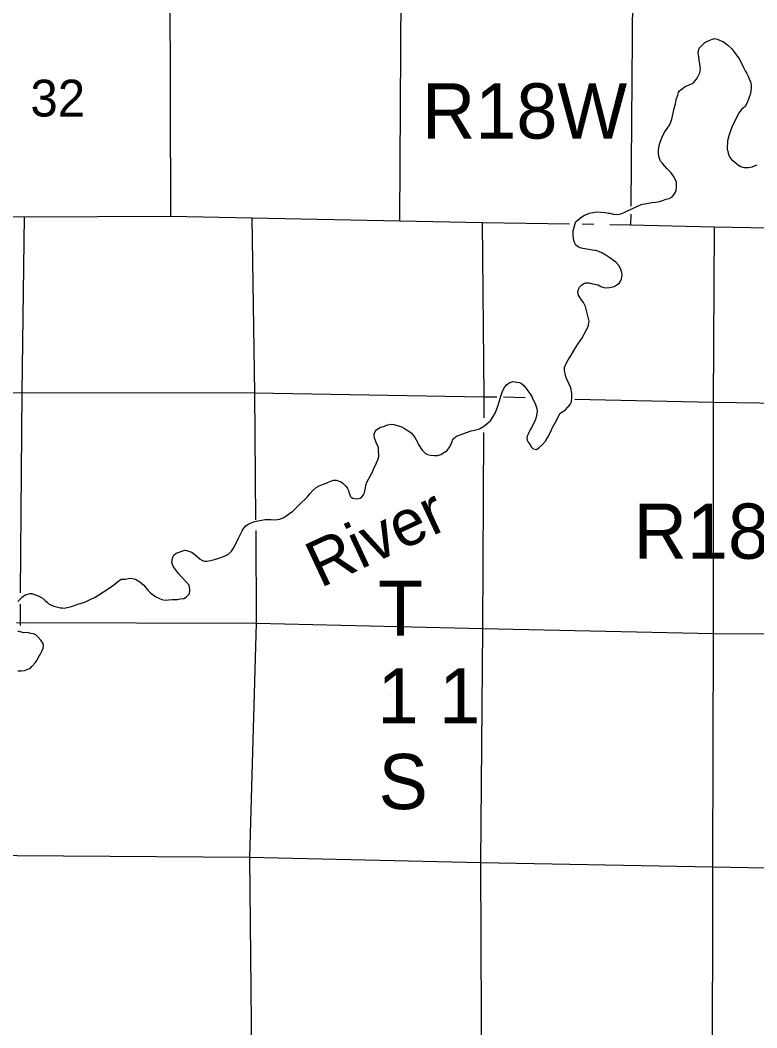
# Model space of a CAD drawing. Extents: x 369523 to 838377, y 495025 to 936819.
# Drawn here: x 613164 to 630067, y 646707 to 669834 of the extents above; entities that cross this region are included whole.
import ezdxf

# ---------------------------------------------------------------- set-up
doc = ezdxf.new("R2010")
doc.units = 0
for name, color, linetype in [('21', 7, 'Continuous'), ('Level 10', 7, 'Continuous'), ('Level 15', 7, 'Continuous'), ('Level 22', 7, 'Continuous'), ('Level 6', 7, 'Continuous')]:
    doc.layers.add(name, color=color, linetype=linetype)

msp = doc.modelspace()

# ---------------------------------------------------------------- linework, layer by layer
at = {"layer": '21'}
msp.add_line((621695, 654327), (621695, 654327), dxfattribs=at)
at = {"layer": 'Level 15'}
for points in [[(605886, 665418), (607991, 665418), (611148, 665368), (613262, 665320), (616612, 665336), (618481, 665296), (621877, 665231), (623770, 665192), (625765, 665158)], [(626061, 665160), (626325, 665151)], [(626693, 665141), (627168, 665140), (629092, 665093), (632435, 665026), (634448, 665035), (636918, 665073)]]:
    msp.add_lwpolyline(points, dxfattribs=at)
at = {"layer": 'Level 22'}
for points in [[(616654, 686505), (616700, 681163), (616598, 675885), (616601, 670709), (616612, 665336)], [(621877, 665231), (621904, 670478), (621874, 675814), (621911, 681087), (621962, 686355)], [(627265, 686234), (627212, 680945), (627217, 675651), (627216, 670404), (627179, 665566)], [(613171, 656688), (613207, 661290), (613262, 665320)], [(618481, 665296), (618538, 661278), (618566, 658369)], [(623812, 660705), (623809, 661193), (623770, 665192)], [(627175, 665382), (627168, 665140)], [(629092, 665093), (629069, 661056), (629065, 655755), (629049, 650405), (629042, 645132), (629075, 639773)], [(602718, 661287), (607982, 661235), (613207, 661290), (618538, 661278), (623799, 661189), (624103, 661186)], [(624755, 661168), (624257, 661183)], [(640672, 661007), (639673, 661005), (634435, 660986), (629069, 661056), (625892, 661130)], [(623804, 639853), (623760, 645102), (623738, 650500), (623784, 655875), (623805, 660371)], [(618570, 658123), (618578, 655993), (618427, 650623), (618478, 645324), (618463, 640081)], [(613172, 655944), (613175, 656434)], [(613081, 656010), (618578, 655993), (623784, 655875), (629065, 655755), (634462, 655732), (639666, 655759), (643998, 655781)], [(607915, 650684), (613094, 650662), (618427, 650623), (623738, 650500), (629049, 650405), (634411, 650303), (639697, 650207)]]:
    msp.add_lwpolyline(points, dxfattribs=at)
at = {"layer": 'Level 6'}
for points in [[(627810, 666861), (627828, 666961), (627851, 667037), (627884, 667136), (627952, 667261), (628010, 667348), (628065, 667427), (628090, 667478), (628119, 667562), (628172, 667807), (628198, 667912), (628219, 668004), (628251, 668115), (628272, 668177), (628294, 668210), (628424, 668314), (628603, 668388), (628685, 668480), (628710, 668530), (628761, 668629), (628776, 668719), (628762, 668835), (628745, 668915), (628734, 669001), (628721, 669071), (628730, 669137), (628755, 669200), (628796, 669248), (628847, 669293), (628873, 669318), (628988, 669373), (629028, 669388), (629099, 669411), (629159, 669400), (629304, 669336), (629395, 669265), (629492, 669175), (629563, 669084), (629616, 669010), (629663, 668953), (629694, 668885), (629741, 668802), (629763, 668750), (629803, 668673), (629837, 668607), (629868, 668552), (629893, 668488), (629922, 668418), (629937, 668350), (629938, 668284), (629931, 668214), (629924, 668150), (629887, 668043), (629843, 667933), (629802, 667854), (629759, 667819), (629719, 667781), (629660, 667716), (629590, 667584), (629497, 667377), (629428, 667181), (629394, 667063), (629387, 666882), (629410, 666781), (629443, 666701), (629484, 666640), (629555, 666583), (629615, 666527), (629694, 666475), (629776, 666456), (629876, 666451), (629960, 666467), (630013, 666491), (630073, 666514)], [(627810, 666861), (627828, 666961), (627851, 667037), (627884, 667136), (627952, 667261), (628010, 667348), (628065, 667427), (628090, 667478), (628119, 667562), (628172, 667807), (628198, 667912), (628219, 668004), (628251, 668115), (628272, 668177), (628294, 668210), (628424, 668314), (628603, 668388), (628685, 668480), (628710, 668530), (628761, 668629), (628776, 668719), (628762, 668835), (628745, 668915), (628734, 669001), (628721, 669071), (628730, 669137), (628755, 669200), (628796, 669248), (628847, 669293), (628873, 669318), (628988, 669373), (629028, 669388), (629099, 669411), (629159, 669400), (629304, 669336), (629395, 669265), (629492, 669175), (629563, 669084), (629616, 669010), (629663, 668953), (629694, 668885), (629741, 668802), (629763, 668750), (629803, 668673), (629837, 668607), (629868, 668552), (629893, 668488), (629922, 668418), (629937, 668350), (629938, 668284), (629931, 668214), (629924, 668150), (629887, 668043), (629843, 667933), (629802, 667854), (629759, 667819), (629719, 667781), (629660, 667716), (629590, 667584), (629497, 667377), (629428, 667181), (629394, 667063), (629387, 666882), (629410, 666781), (629443, 666701), (629484, 666640), (629555, 666583), (629615, 666527), (629694, 666475), (629776, 666456), (629876, 666451), (629960, 666467), (630013, 666491), (630073, 666514)], [(626109, 662626), (626194, 662801), (626222, 662928), (626136, 663261), (626088, 663354), (626040, 663420), (626011, 663459), (625988, 663499), (625970, 663537), (625957, 663599), (625984, 663679), (626001, 663708), (626033, 663744), (626049, 663756), (626092, 663785), (626124, 663799), (626142, 663802), (626174, 663802), (626222, 663803), (626300, 663782), (626424, 663756), (626491, 663719), (626553, 663702), (626603, 663693), (626683, 663696), (626770, 663713), (626808, 663728), (626853, 663762), (626885, 663783), (626913, 663805), (626932, 663832), (626961, 663894), (626974, 663980), (626967, 664044), (626946, 664112), (626905, 664194), (626830, 664281), (626691, 664379), (626600, 664443), (626524, 664484), (626443, 664523), (626371, 664546), (626287, 664557), (626163, 664575), (626075, 664594), (626015, 664611), (625968, 664634), (625916, 664673), (625889, 664713), (625868, 664777), (625851, 664895), (625853, 664999), (625901, 665164), (625924, 665218), (625958, 665247), (626021, 665294), (626054, 665320), (626112, 665355), (626173, 665378), (626223, 665405), (626342, 665429), (626410, 665434), (626488, 665431), (626590, 665416), (626654, 665407), (626698, 665402), (626770, 665385), (626840, 665376), (626910, 665383), (626970, 665400), (627039, 665429), (627081, 665448), (627412, 665605), (627450, 665612), (627544, 665623), (627655, 665649), (627739, 665654), (627793, 665663), (627831, 665669), (627900, 665693), (627988, 665722), (628053, 665741), (628125, 665778), (628164, 665825), (628199, 665883), (628216, 665930), (628227, 665984), (628227, 666046), (628222, 666106), (628207, 666156), (628152, 666257), (628091, 666338), (628054, 666376), (628001, 666431), (627949, 666490), (627898, 666558), (627884, 666569), (627857, 666597), (627826, 666679), (627809, 666758), (627810, 666861)], [(626109, 662626), (626194, 662801), (626222, 662928), (626136, 663261), (626088, 663354), (626040, 663420), (626011, 663459), (625988, 663499), (625970, 663537), (625957, 663599), (625984, 663679), (626001, 663708), (626033, 663744), (626049, 663756), (626092, 663785), (626124, 663799), (626142, 663802), (626174, 663802), (626222, 663803), (626300, 663782), (626424, 663756), (626491, 663719), (626553, 663702), (626603, 663693), (626683, 663696), (626770, 663713), (626808, 663728), (626853, 663762), (626885, 663783), (626913, 663805), (626932, 663832), (626961, 663894), (626974, 663980), (626967, 664044), (626946, 664112), (626905, 664194), (626830, 664281), (626691, 664379), (626600, 664443), (626524, 664484), (626443, 664523), (626371, 664546), (626287, 664557), (626163, 664575), (626075, 664594), (626015, 664611), (625968, 664634), (625916, 664673), (625889, 664713), (625868, 664777), (625851, 664895), (625853, 664999), (625901, 665164), (625924, 665218), (625958, 665247), (626021, 665294), (626054, 665320), (626112, 665355), (626173, 665378), (626223, 665405), (626342, 665429), (626410, 665434), (626488, 665431), (626590, 665416), (626654, 665407), (626698, 665402), (626770, 665385), (626840, 665376), (626910, 665383), (626970, 665400), (627039, 665429), (627081, 665448), (627412, 665605), (627450, 665612), (627544, 665623), (627655, 665649), (627739, 665654), (627793, 665663), (627831, 665669), (627900, 665693), (627988, 665722), (628053, 665741), (628125, 665778), (628164, 665825), (628199, 665883), (628216, 665930), (628227, 665984), (628227, 666046), (628222, 666106), (628207, 666156), (628152, 666257), (628091, 666338), (628054, 666376), (628001, 666431), (627949, 666490), (627898, 666558), (627884, 666569), (627857, 666597), (627826, 666679), (627809, 666758), (627810, 666861)], [(622332, 660048), (622356, 660012), (622389, 659966), (622425, 659925), (622468, 659892), (622514, 659866), (622582, 659847), (622670, 659843), (622740, 659846), (622817, 659863), (622901, 659922), (622964, 659961), (623017, 660032), (623044, 660085), (623077, 660163), (623088, 660195), (623114, 660232), (623135, 660256), (623177, 660289), (623407, 660374), (623515, 660406), (623598, 660425), (623702, 660455), (623795, 660512), (623882, 660574), (623953, 660641), (624017, 660734), (624070, 660833), (624123, 660978), (624164, 661101), (624196, 661205), (624217, 661272), (624250, 661348), (624287, 661415), (624324, 661461), (624350, 661484), (624374, 661504), (624399, 661515), (624431, 661529), (624465, 661538), (624525, 661535), (624563, 661527), (624621, 661518), (624667, 661493), (624730, 661440), (624793, 661356), (624862, 661267), (624911, 661184), (624926, 661138), (624979, 661035), (625004, 660965), (625023, 660911), (625026, 660865), (625022, 660809), (625004, 660725), (624979, 660644), (624954, 660592), (624917, 660521), (624891, 660473), (624866, 660430), (624837, 660368), (624819, 660336), (624794, 660285), (624791, 660231), (624796, 660191), (624820, 660147), (624867, 660090), (624900, 660036), (624930, 660003), (624946, 659995), (625008, 659982), (625075, 660023), (625148, 660092), (625221, 660175), (625272, 660262), (625324, 660363), (625390, 660498), (625450, 660611), (625491, 660694), (625546, 660807), (625674, 660893), (625784, 661015), (625811, 661077), (625826, 661182), (625820, 661276), (625797, 661396), (625760, 661477), (625710, 661591), (625687, 661646), (625675, 661688), (625666, 661726), (625655, 661786), (625655, 661830), (625656, 661864), (625689, 661951), (625742, 662036), (625798, 662133), (625882, 662272), (625962, 662399), (626048, 662525), (626109, 662626)], [(622332, 660048), (622356, 660012), (622389, 659966), (622425, 659925), (622468, 659892), (622514, 659866), (622582, 659847), (622670, 659843), (622740, 659846), (622817, 659863), (622901, 659922), (622964, 659961), (623017, 660032), (623044, 660085), (623077, 660163), (623088, 660195), (623114, 660232), (623135, 660256), (623177, 660289), (623407, 660374), (623515, 660406), (623598, 660425), (623702, 660455), (623795, 660512), (623882, 660574), (623953, 660641), (624017, 660734), (624070, 660833), (624123, 660978), (624164, 661101), (624196, 661205), (624217, 661272), (624250, 661348), (624287, 661415), (624324, 661461), (624350, 661484), (624374, 661504), (624399, 661515), (624431, 661529), (624465, 661538), (624525, 661535), (624563, 661527), (624621, 661518), (624667, 661493), (624730, 661440), (624793, 661356), (624862, 661267), (624911, 661184), (624926, 661138), (624979, 661035), (625004, 660965), (625023, 660911), (625026, 660865), (625022, 660809), (625004, 660725), (624979, 660644), (624954, 660592), (624917, 660521), (624891, 660473), (624866, 660430), (624837, 660368), (624819, 660336), (624794, 660285), (624791, 660231), (624796, 660191), (624820, 660147), (624867, 660090), (624900, 660036), (624930, 660003), (624946, 659995), (625008, 659982), (625075, 660023), (625148, 660092), (625221, 660175), (625272, 660262), (625324, 660363), (625390, 660498), (625450, 660611), (625491, 660694), (625546, 660807), (625674, 660893), (625784, 661015), (625811, 661077), (625826, 661182), (625820, 661276), (625797, 661396), (625760, 661477), (625710, 661591), (625687, 661646), (625675, 661688), (625666, 661726), (625655, 661786), (625655, 661830), (625656, 661864), (625689, 661951), (625742, 662036), (625798, 662133), (625882, 662272), (625962, 662399), (626048, 662525), (626109, 662626)], [(617349, 657431), (617395, 657420), (617447, 657421), (617529, 657436), (617626, 657458), (617700, 657481), (617789, 657512), (617885, 657550), (617944, 657579), (618011, 657644), (618058, 657717), (618110, 657813), (618172, 657945), (618209, 658023), (618256, 658112), (618297, 658177), (618342, 658227), (618396, 658264), (618447, 658293), (618521, 658320), (618618, 658346), (618708, 658359), (618781, 658372), (618847, 658375), (618921, 658370), (618993, 658365), (619065, 658372), (619121, 658381), (619214, 658423), (619418, 658564), (619548, 658694), (619626, 658769), (619693, 658833), (619748, 658887), (619821, 658967), (619878, 659036), (619959, 659105), (620026, 659146), (620098, 659175), (620169, 659202), (620217, 659223), (620292, 659256), (620350, 659273), (620414, 659276), (620532, 659236), (620569, 659206), (620605, 659169), (620635, 659141), (620670, 659098), (620686, 659070), (620695, 659038), (620703, 659000), (620726, 658940), (620734, 658916), (620745, 658902), (620761, 658885), (620797, 658867), (620839, 658852), (620889, 658847), (620933, 658853), (620965, 658866), (621006, 658894), (621042, 658943), (621063, 658985), (621072, 659028), (621093, 659144), (621110, 659216), (621244, 659455), (621281, 659545), (621341, 659676), (621381, 659767), (621394, 659823), (621390, 659979), (621383, 660035), (621359, 660091), (621334, 660143), (621297, 660248), (621288, 660304), (621289, 660342), (621308, 660395), (621332, 660423), (621371, 660458), (621409, 660476), (621461, 660497), (621510, 660512), (621554, 660529), (621598, 660545), (621683, 660565), (621741, 660557), (621818, 660533), (621902, 660506), (621986, 660465), (622083, 660400), (622146, 660353), (622176, 660320), (622205, 660278), (622223, 660254), (622280, 660147), (622299, 660105), (622311, 660083), (622332, 660048)], [(617349, 657431), (617395, 657420), (617447, 657421), (617529, 657436), (617626, 657458), (617700, 657481), (617789, 657512), (617885, 657550), (617944, 657579), (618011, 657644), (618058, 657717), (618110, 657813), (618172, 657945), (618209, 658023), (618256, 658112), (618297, 658177), (618342, 658227), (618396, 658264), (618447, 658293), (618521, 658320), (618618, 658346), (618708, 658359), (618781, 658372), (618847, 658375), (618921, 658370), (618993, 658365), (619065, 658372), (619121, 658381), (619214, 658423), (619418, 658564), (619548, 658694), (619626, 658769), (619693, 658833), (619748, 658887), (619821, 658967), (619878, 659036), (619959, 659105), (620026, 659146), (620098, 659175), (620169, 659202), (620217, 659223), (620292, 659256), (620350, 659273), (620414, 659276), (620532, 659236), (620569, 659206), (620605, 659169), (620635, 659141), (620670, 659098), (620686, 659070), (620695, 659038), (620703, 659000), (620726, 658940), (620734, 658916), (620745, 658902), (620761, 658885), (620797, 658867), (620839, 658852), (620889, 658847), (620933, 658853), (620965, 658866), (621006, 658894), (621042, 658943), (621063, 658985), (621072, 659028), (621093, 659144), (621110, 659216), (621244, 659455), (621281, 659545), (621341, 659676), (621381, 659767), (621394, 659823), (621390, 659979), (621383, 660035), (621359, 660091), (621334, 660143), (621297, 660248), (621288, 660304), (621289, 660342), (621308, 660395), (621332, 660423), (621371, 660458), (621409, 660476), (621461, 660497), (621510, 660512), (621554, 660529), (621598, 660545), (621683, 660565), (621741, 660557), (621818, 660533), (621902, 660506), (621986, 660465), (622083, 660400), (622146, 660353), (622176, 660320), (622205, 660278), (622223, 660254), (622280, 660147), (622299, 660105), (622311, 660083), (622332, 660048)], [(613108, 656488), (613214, 656600), (613277, 656643), (613392, 656675), (613434, 656674), (613491, 656652), (613559, 656627), (613605, 656604), (613671, 656577), (613740, 656516), (613791, 656465), (613833, 656429), (613934, 656385), (614086, 656343), (614128, 656344), (614176, 656342), (614343, 656379), (614508, 656437), (614645, 656480), (614768, 656534), (614885, 656589), (614972, 656641), (615079, 656710), (615210, 656796), (615263, 656837), (615310, 656878), (615401, 656946), (615478, 657001), (615568, 657008), (615694, 657024), (615814, 657004), (615910, 656945), (616003, 656863), (616093, 656752), (616156, 656693), (616275, 656600), (616411, 656534), (616486, 656519), (616569, 656533), (616653, 656538), (616777, 656536), (616834, 656553), (616916, 656564), (616982, 656601), (617049, 656666), (617057, 656764), (617040, 656864), (616983, 656939), (616861, 657064), (616794, 657137), (616751, 657194), (616705, 657260), (616668, 657315), (616645, 657389), (616661, 657485), (616692, 657552), (616744, 657603), (616940, 657668), (616982, 657660), (617055, 657639), (617107, 657614), (617171, 657573), (617234, 657518), (617291, 657467), (617349, 657431)], [(613108, 656488), (613214, 656600), (613277, 656643), (613392, 656675), (613434, 656674), (613491, 656652), (613559, 656627), (613605, 656604), (613671, 656577), (613740, 656516), (613791, 656465), (613833, 656429), (613934, 656385), (614086, 656343), (614128, 656344), (614176, 656342), (614343, 656379), (614508, 656437), (614645, 656480), (614768, 656534), (614885, 656589), (614972, 656641), (615079, 656710), (615210, 656796), (615263, 656837), (615310, 656878), (615401, 656946), (615478, 657001), (615568, 657008), (615694, 657024), (615814, 657004), (615910, 656945), (616003, 656863), (616093, 656752), (616156, 656693), (616275, 656600), (616411, 656534), (616486, 656519), (616569, 656533), (616653, 656538), (616777, 656536), (616834, 656553), (616916, 656564), (616982, 656601), (617049, 656666), (617057, 656764), (617040, 656864), (616983, 656939), (616861, 657064), (616794, 657137), (616751, 657194), (616705, 657260), (616668, 657315), (616645, 657389), (616661, 657485), (616692, 657552), (616744, 657603), (616940, 657668), (616982, 657660), (617055, 657639), (617107, 657614), (617171, 657573), (617234, 657518), (617291, 657467), (617349, 657431)], [(613112, 654901), (613184, 654898), (613266, 654909), (613343, 654936), (613393, 654957), (613440, 655006), (613511, 655087), (613554, 655148), (613585, 655212), (613620, 655277), (613663, 655353), (613692, 655418), (613699, 655474), (613692, 655530), (613641, 655605), (613576, 655675), (613522, 655724), (613469, 655753), (613409, 655756), (613355, 655771), (613289, 655780), (613247, 655776), (613113, 655812)], [(613112, 654901), (613184, 654898), (613266, 654909), (613343, 654936), (613393, 654957), (613440, 655006), (613511, 655087), (613554, 655148), (613585, 655212), (613620, 655277), (613663, 655353), (613692, 655418), (613699, 655474), (613692, 655530), (613641, 655605), (613576, 655675), (613522, 655724), (613469, 655753), (613409, 655756), (613355, 655771), (613289, 655780), (613247, 655776), (613113, 655812)]]:
    msp.add_lwpolyline(points, dxfattribs=at)

# ---------------------------------------------------------------- texts
at = {"layer": '21'}
for s, height, p in [('R18W', 1267.2, (622383, 667117)), ('R18W', 1267.2, (627239, 657473)), ('T', 1267, (621372, 655705)), ('1 1', 1267.2, (621364, 653693)), ('S', 1267, (621388, 651726))]:
    msp.add_text(s, height=height, dxfattribs=at).set_placement(p)
at = {"layer": 'Level 10'}
msp.add_text('River', height=1056, rotation=25, dxfattribs=at).set_placement((620052, 656794))
at = {"layer": 'Level 22'}
msp.add_text('32', height=844.8, dxfattribs=at).set_placement((613398, 667623))

doc.saveas('drawing.dxf')
